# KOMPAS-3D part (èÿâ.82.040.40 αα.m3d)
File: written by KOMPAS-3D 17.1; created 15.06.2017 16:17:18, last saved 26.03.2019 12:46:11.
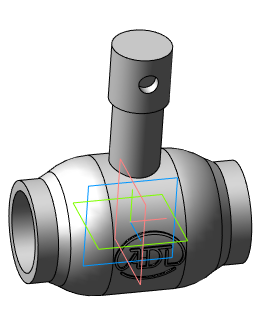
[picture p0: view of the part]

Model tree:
1. Операция без истории:2  (labels: Сталь 20  ГОСТ 1050-88)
